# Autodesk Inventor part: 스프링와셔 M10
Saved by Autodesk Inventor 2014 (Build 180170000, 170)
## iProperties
Created: 2026-03
Part Number: 스프링와셔 M10
Material: 일반
Document SubType Name: Modeling
Designer: dg
Density: 1 g/cm^3
Appearance: 기본값
Author: dg
Author: jhkim
Description: 스프링 잠금 와셔
Creation Date: 2025-06-27
Sending System: Autodesk Inventor 2026
Preprocessor: ST-DEVELOPER v20.1
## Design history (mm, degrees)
node "스프링와셔 M101"
body "Solid1"
node "기준1"
